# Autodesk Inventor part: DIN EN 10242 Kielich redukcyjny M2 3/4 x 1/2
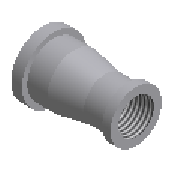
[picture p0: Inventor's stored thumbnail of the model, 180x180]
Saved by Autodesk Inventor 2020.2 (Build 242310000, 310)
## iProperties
Manager: www.cadconsulting.pl
Company: Fabian Stasiak CAD Consulting
Created: 2014-02
Part Number: DIN EN 10242 Kielich redukcyjny M2 3/4 x 1/2
Material: Żelazo, ciągliwe
Description: Kielich
Document SubType Name: Modeling
Standard: DIN EN 10242
Designer: F.Stasiak
Standards Organization: DIN
Language: pl-PL
Size Designation: 3/4 x 1/2
Categories: <MemberInstance><Categories><Category DisplayName="Rury cienko- i grubościenne" InternalName="4347fa0f-2144-441d-94cd-e3e15c92b736" Mnemonic="TUBEANDPIPE"><Cate
Density: 7.15 g/cm^3
Appearance: Częściowo polerowana
Catalog Web Link: www.expertbooks.pl
IsCustomPart: 0
NAME: PIPING: DIN EN 10242 Socket Reducing M2
DATA: <meta><inlinegroups number="1" deflen="3"></inlinegroups><connections number="2"></connections><angles><a>3.14159265358979</a></angles></meta>
Author: F.Stasiak
Subject: Zbiór ćwiczeń. Autodesk Inventor 2020. Kurs Professional
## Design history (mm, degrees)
sketch "Sketch1"
  geometry: L1 (0, 16.32)-(5.44, 16.32); L2 (5.44, 16.32)-(5.44, 13.6); L3 (34.66, 10.85)-(34.66, 13.02); L4 (34.66, 13.02)-(39, 13.02); L5 (0, 0)-(39, 0); L6 (5.44, 13.6)-(15, 13.6); L7 (34.66, 10.85)-(26, 10.85); L8 (26, 10.85)-(15, 13.6); L9 (15, 13.6)-(15, 12.059); L10 (26, 9.316)-(39, 9.316); L11 (26, 10.85)-(26, 9.316); L12 (15, 12.059)-(0, 12.059); L13 (0, 16.32)-(0, 12.059); L14 (39, 13.02)-(39, 9.316); L15 (0, 12.059)-(0, 0); L16 (39, 9.316)-(39, 0); L17 (15, 12.059)-(26, 9.316); L18 (15, 12.059)-(15, 0); L19 (26, 9.316)-(26, 0)
  constraints: 38 end point, 8 parallel, 3 perpendicular, 2 horizontal, 2 point on line, 1 vertical, 1 other
  dimensions: "d0" = 24.117 diameter of L12.end L5 (= MD1); "d1" = 18.631 diameter of L10.end L5 (= MD2); "d2" = 32.64 diameter of L1.start L5 (= H1); "d3" = 26.04 diameter of L4 L5 (= H2); "d4" = 27.2 diameter of L6 L5 (= D1); "d5" = 21.7 diameter of L7 L5 (= D2); "d6" = 5.44 distance of L1.start L1.end (= EE1); "d7" = 39 distance between parallel lines of L14 L13 (= A); "d8" = 11 distance between parallel lines of L11 L9 (= Z2); "d9" = 4.34 distance of L3.end L4.end (= EE2); "d10" = 15 distance between parallel lines of L13 L9 (= 0.5 x A - 0.5 x Z1)
revolve "Revolution1" sketch "Sketch1" stored, may be unused: angle "d26" = 90 deg
workpoint "Work Point1"
workpoint "Work Point2"
workaxis "Work Axis1"
workpoint "Work Point3"
workaxis "Work Axis2"
workpoint "Work Point4"
body "Solid1"
feature "Gwint1" dims "d32" = 10, "d33" = 0
feature "Gwint2" dims "d34" = 10, "d35" = 0
other parameters: "MD1" = 24.117 [user parameter; used in 1 equation term], "MD2" = 18.631 [user parameter; used in 1 equation term], "EE1" = 5.44 (= 0.2 x D1) [user parameter; used in 1 equation term], "EE2" = 4.34 (= 0.2 x D2) [user parameter; used in 1 equation term], "D1" = 27.2 [user parameter; used in 3 equation terms], "D2" = 21.7 [user parameter; used in 3 equation terms], "H1" = 32.64 (= 1.2 x D1) [user parameter; used in 1 equation term], "H2" = 26.04 (= 1.2 x D2) [user parameter; used in 1 equation term], "Z2" = 11 [user parameter; used in 1 equation term], "A" = 39 [user parameter; used in 2 equation terms], "Z1" = 9 [user parameter; used in 1 equation term], "Size_Designation" = 12.345 [user parameter]
